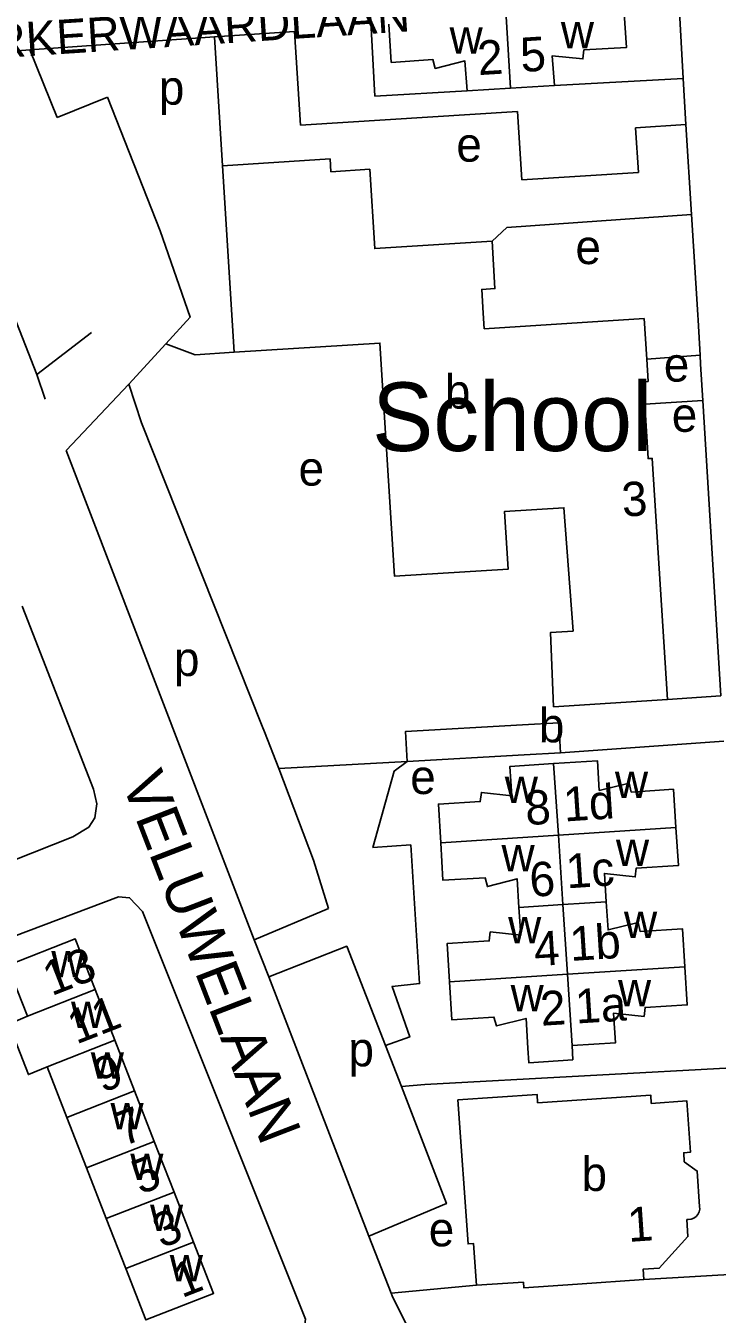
# Model space of a CAD drawing. Extents: x 159675 to 162108, y 386471 to 388472.
# Drawn here: x 160273.4 to 160354.1, y 387507.9 to 387658.2 of the extents above; entities that cross this region are included whole.
import ezdxf

# ---------------------------------------------------------------- set-up
doc = ezdxf.new("R2010")
doc.units = 0
for name, color, linetype in [('BLT_Basislijn', 7, 'Continuous'), ('BLT_Bebouwing', 7, 'Continuous'), ('BLT_Bebouwing_beschrifting', 7, 'Continuous'), ('BLT_Centroide', 7, 'Continuous'), ('BLT_Huisnummer', 7, 'Continuous'), ('BLT_Huisnummer_ tussenligend', 7, 'Continuous'), ('BLT_Onderverdeling_panden', 7, 'Continuous'), ('BLT_Straatnaam', 7, 'Continuous'), ('BLT_Straatnaam_verkleind', 7, 'Continuous')]:
    doc.layers.add(name, color=color, linetype=linetype)

msp = doc.modelspace()

# ---------------------------------------------------------------- linework, layer by layer
at = {"layer": 'BLT_Basislijn'}
for p, q in [((160312.42, 387682.86), (160314.09, 387650.02)), ((160273.87, 387655.42), (160295.39, 387656.92)), ((160295.39, 387656.92), (160304.73, 387657.57)), ((160295.39, 387656.92), (160296.34, 387641.9)), ((160304.73, 387657.57), (160305.42, 387646.63)), ((160273.87, 387655.42), (160268.65, 387655.02)), ((160273.87, 387655.42), (160277.03, 387647.51)), ((160335.06, 387651.26), (160350.07, 387652.07)), ((160350.07, 387652.07), (160350.39, 387646.69)), ((160324.88, 387650.63), (160314.09, 387650.02)), ((160277.03, 387647.51), (160282.91, 387649.88)), ((160305.42, 387646.63), (160330.75, 387648.23)), ((160331.26, 387640.23), (160330.75, 387648.23)), ((160350.39, 387646.69), (160344.53, 387646.32)), ((160344.53, 387646.32), (160344.86, 387641.09)), ((160274.68, 387617.54), (160264.83, 387642.61)), ((160344.86, 387641.09), (160331.26, 387640.23)), ((160351.05, 387636.2), (160351.78, 387624.49)), ((160281.06, 387622.42), (160274.68, 387617.54)), ((160285.41, 387616.39), (160289.72, 387621.11)), ((160345.84, 387619.34), (160352.05, 387619.79)), ((160275.66, 387614.64), (160274.68, 387617.54)), ((160278.08, 387608.68), (160285.41, 387616.39)), ((160345.59, 387614.09), (160352.36, 387614.52)), ((160354.48, 387580.05), (160352.36, 387614.52)), ((160300.04, 387551.59), (160278.08, 387608.68)), ((160348.24, 387579.61), (160354.48, 387580.05)), ((160335.78, 387573.39), (160354.84, 387574.74)), ((160317.87, 387572.39), (160302.89, 387571.55)), ((160308.7, 387555.24), (160300.04, 387551.59)), ((160301.74, 387547.27), (160300.04, 387551.59)), ((160313.41, 387517), (160301.74, 387547.27)), ((160316, 387510.37), (160313.41, 387517)), ((160345.48, 387511.95), (160358.81, 387512.71)), ((160325.97, 387511.3), (160316, 387510.37))]:
    msp.add_line(p, q, dxfattribs=at)
for points in [[(160350.07, 387652.07), (160348.33, 387683.87), (160348.64, 387684.98)], [(160282.91, 387649.88), (160289.07, 387634.3), (160292.57, 387624.22), (160289.72, 387621.11)], [(160351.05, 387636.2), (160350.39, 387646.69)], [(160327.78, 387633.09), (160329.51, 387634.7), (160351.05, 387636.2)], [(160351.78, 387624.49), (160351.82, 387623.88), (160352.05, 387619.79)], [(160289.72, 387621.11), (160293.14, 387619.85), (160297.71, 387620.13)], [(160352.05, 387619.79), (160352.11, 387618.74), (160352.36, 387614.52)], [(160300.98, 387576.52), (160286.9, 387611.91), (160285.41, 387616.39)], [(160225.28, 387549.74), (160227.62, 387544.2), (160234.82, 387546.54), (160262.65, 387557.18), (160278.86, 387563.59), (160280.74, 387564.74), (160281.44, 387565.8), (160281.66, 387567.45), (160281.28, 387569.14), (160273.3, 387589.61), (160272.95, 387590.5)], [(160302.89, 387571.55), (160301.24, 387575.85), (160300.98, 387576.52)], [(160315.35, 387539.24), (160318.18, 387540.26), (160316.12, 387546.15), (160319.32, 387546.48), (160318.29, 387562.65), (160313.89, 387562.37), (160316.38, 387571.27), (160317.87, 387572.39)], [(160308.7, 387555.24), (160306.96, 387560.89), (160302.89, 387571.55)], [(160279.46, 387491.22), (160280.02, 387491.49), (160298.16, 387499.55), (160303.51, 387501.62), (160305.61, 387504), (160306.01, 387507.33), (160287.01, 387554.89), (160285.5, 387556.48), (160284.21, 387556.61), (160258.21, 387546.8)], [(160315.35, 387539.24), (160310.84, 387550.83), (160301.74, 387547.27)], [(160317.22, 387534.45), (160315.35, 387539.24)], [(160317.22, 387534.45), (160319.95, 387534.71), (160357.2, 387536.71)], [(160313.41, 387517), (160322.46, 387520.8), (160317.22, 387534.45)], [(160318.2, 387505.88), (160316.12, 387510.05), (160316, 387510.37)]]:
    msp.add_lwpolyline(points, dxfattribs=at)
at = {"layer": 'BLT_Bebouwing'}
for p, q in [((160324.88, 387650.63), (160329.94, 387650.95)), ((160329.94, 387650.95), (160335.06, 387651.26)), ((160296.34, 387641.9), (160297.71, 387620.13)), ((160345.84, 387619.34), (160345.53, 387624.08)), ((160346.01, 387616.73), (160345.84, 387619.34)), ((160334.96, 387578.77), (160348.24, 387579.61)), ((160331.54, 387573.15), (160317.87, 387572.39)), ((160331.54, 387573.15), (160335.78, 387573.39)), ((160281.47, 387545.77), (160283.77, 387539.86)), ((160283.77, 387539.86), (160286.07, 387533.95)), ((160278.17, 387530.87), (160275.87, 387536.78)), ((160286.07, 387533.95), (160288.38, 387528.04)), ((160280.48, 387524.97), (160278.17, 387530.87)), ((160288.38, 387528.04), (160290.68, 387522.14)), ((160282.78, 387519.06), (160280.48, 387524.97)), ((160290.68, 387522.14), (160292.95, 387516.32)), ((160285.05, 387513.24), (160282.78, 387519.06))]:
    msp.add_line(p, q, dxfattribs=at)
for points in [[(160335.06, 387651.26), (160334.81, 387654.73), (160338.39, 387654.35), (160338.51, 387655.4), (160343.45, 387655.68), (160343.15, 387660.24)], [(160315.73, 387658.41), (160316.03, 387653.95), (160320.86, 387654.29), (160321.16, 387653.24), (160324.62, 387654.12), (160324.88, 387650.63)], [(160327.78, 387633.09), (160314.1, 387632.23), (160313.52, 387641.48), (160308.99, 387641.19), (160308.89, 387642.69), (160296.34, 387641.9)], [(160345.53, 387624.08), (160326.87, 387622.87), (160326.75, 387624.7), (160326.58, 387627.47), (160328.12, 387627.57), (160327.78, 387633.09)], [(160297.71, 387620.13), (160314.71, 387621.2), (160316.42, 387593.99), (160329.65, 387594.82), (160329.23, 387601.55), (160336.17, 387601.99), (160337.23, 387587.6), (160334.59, 387587.42), (160334.96, 387578.77)], [(160345.59, 387614.09), (160345.41, 387616.69), (160346.01, 387616.73)], [(160348.24, 387579.61), (160346.47, 387607.75), (160345.99, 387607.72), (160345.59, 387614.09)], [(160317.87, 387572.39), (160317.67, 387575.87), (160331.34, 387576.65)], [(160335.78, 387573.39), (160335.59, 387576.89), (160331.34, 387576.65)], [(160321.79, 387562.9), (160321.53, 387567.42), (160326.41, 387567.7), (160326.54, 387568.77), (160330.11, 387568.37), (160329.87, 387571.81), (160334.97, 387572.14)], [(160334.97, 387572.14), (160340.07, 387572.48), (160340.28, 387569.01), (160343.78, 387569.85), (160344.02, 387568.82), (160348.94, 387569.15), (160349.24, 387564.69)], [(160349.24, 387564.69), (160349.53, 387560.24), (160344.6, 387559.96), (160344.48, 387558.92), (160340.89, 387559.33), (160341.1, 387556.03)], [(160330.92, 387555.36), (160330.7, 387558.7), (160327.24, 387557.8), (160326.98, 387558.82), (160322.05, 387558.53), (160321.79, 387562.9)], [(160341.1, 387556.03), (160341.32, 387552.74), (160344.83, 387553.59), (160345.06, 387552.57), (160349.99, 387552.88), (160350.27, 387548.43)], [(160322.83, 387546.68), (160322.56, 387551.16), (160327.46, 387551.46), (160327.57, 387552.51), (160331.14, 387552.12), (160330.92, 387555.36)], [(160273.57, 387542.69), (160271.26, 387548.6), (160279.16, 387551.68), (160281.47, 387545.77)], [(160350.27, 387548.43), (160350.56, 387543.99), (160345.64, 387543.7), (160345.52, 387542.64), (160341.96, 387543.03), (160342.19, 387539.58), (160337.12, 387539.26)], [(160337.12, 387539.26), (160337.19, 387537.59), (160332.07, 387537.24), (160331.97, 387538.93), (160331.76, 387542.41), (160328.3, 387541.53), (160328.01, 387542.57), (160323.09, 387542.25), (160322.83, 387546.68)], [(160275.87, 387536.78), (160273.69, 387535.86), (160271.4, 387541.73), (160273.57, 387542.69)], [(160352, 387520.48), (160351.73, 387524.59), (160350.2, 387525.69), (160350.15, 387526.73), (160350.93, 387526.79), (160350.52, 387532.78), (160346.35, 387532.49), (160346.29, 387533.47), (160333.1, 387532.57), (160333.03, 387533.55), (160323.81, 387532.91), (160324.99, 387516.1), (160325.63, 387516.14), (160325.97, 387511.3)], [(160350.68, 387518.95), (160351.01, 387518.99), (160351.31, 387519.11), (160351.58, 387519.3), (160351.79, 387519.55), (160351.93, 387519.84), (160352.01, 387520.16), (160352, 387520.48)], [(160345.48, 387511.95), (160345.4, 387513.14), (160347.29, 387513.27), (160350.64, 387516.95), (160350.51, 387518.94), (160350.68, 387518.95)], [(160292.95, 387516.32), (160295.29, 387510.32), (160287.39, 387507.24), (160285.05, 387513.24)], [(160325.97, 387511.3), (160331.44, 387511.63), (160331.48, 387510.99), (160337.77, 387511.42), (160345.48, 387511.95)]]:
    msp.add_lwpolyline(points, dxfattribs=at)
at = {"layer": 'BLT_Onderverdeling_panden'}
for p, q in [((160329.42, 387659.32), (160329.94, 387650.95)), ((160334.97, 387572.14), (160335.52, 387563.79)), ((160349.24, 387564.69), (160335.52, 387563.79)), ((160335.52, 387563.79), (160321.79, 387562.9)), ((160335.52, 387563.79), (160336.05, 387555.7)), ((160336.05, 387555.7), (160330.92, 387555.36)), ((160341.1, 387556.03), (160336.05, 387555.7)), ((160336.05, 387555.7), (160336.58, 387547.56)), ((160350.27, 387548.43), (160336.58, 387547.56)), ((160336.58, 387547.56), (160322.83, 387546.68)), ((160336.58, 387547.56), (160337.12, 387539.26)), ((160273.57, 387542.69), (160281.47, 387545.77)), ((160275.87, 387536.78), (160283.77, 387539.86)), ((160278.17, 387530.87), (160286.07, 387533.95)), ((160280.48, 387524.97), (160288.38, 387528.04)), ((160282.78, 387519.06), (160290.68, 387522.14)), ((160285.05, 387513.24), (160292.95, 387516.32))]:
    msp.add_line(p, q, dxfattribs=at)

# ---------------------------------------------------------------- texts
at = {"layer": 'BLT_Bebouwing_beschrifting'}
msp.add_text('School', height=8, dxfattribs=at).set_placement((160313.79, 387608.61))
at = {"layer": 'BLT_Centroide'}
for s, p in [('w', (160322.83, 387654.97)), ('w', (160335.81, 387655.59)), ('p', (160288.91, 387649.02)), ('e', (160323.62, 387642.37)), ('e', (160337.51, 387630.42)), ('e', (160347.82, 387616.71)), ('b', (160322.28, 387613.55)), ('e', (160348.75, 387610.85)), ('e', (160305.21, 387604.57)), ('p', (160290.68, 387582.36)), ('b', (160333.24, 387574.62)), ('e', (160318.24, 387568.59)), ('w', (160329.27, 387567.53)), ('w', (160342.12, 387568.12)), ('w', (160342.24, 387560.19)), ('w', (160328.89, 387559.56)), ('w', (160329.66, 387551.19)), ('w', (160343.18, 387551.78)), ('w', (160276.37, 387547.19)), ('w', (160342.48, 387543.84)), ('w', (160329.95, 387543.25)), ('w', (160278.67, 387541.28)), ('p', (160311.03, 387536.82)), ('w', (160280.97, 387535.38)), ('w', (160283.27, 387529.47)), ('w', (160285.58, 387523.56)), ('b', (160338.22, 387522.28)), ('w', (160287.88, 387517.62)), ('e', (160320.4, 387515.82)), ('w', (160290.19, 387511.72))]:
    msp.add_text(s, height=4, dxfattribs=at).set_placement(p)
at = {"layer": 'BLT_Huisnummer'}
for s, rotation, p in [('2', 3.5511, (160326.2, 387652.46)), ('5', 3.5511, (160331.2, 387652.82)), ('3', 3.602, (160343.03, 387600.94)), ('8', 3.7485, (160331.77, 387564.95)), ('1d', 3.7485, (160336.23, 387565.38)), ('1c', 3.7883, (160336.52, 387557.58)), ('1b', 3.6573, (160336.96, 387549.11)), ('13', 21.2956, (160276.39, 387544.99)), ('2', 3.5952, (160333.53, 387541.55)), ('1a', 3.5952, (160337.6, 387541.81)), ('9', 21.2918, (160282.31, 387533.69)), ('5', 21.2967, (160286.73, 387521.82)), ('1', 3.9041, (160343.71, 387516.33)), ('1', 21.2932, (160291.59, 387509.76))]:
    msp.add_text(s, height=4, rotation=rotation, dxfattribs=at).set_placement(p)
at = {"layer": 'BLT_Huisnummer_ tussenligend'}
for s, rotation, p in [('6', 3.7883, (160332.28, 387556.58)), ('4', 3.5787, (160332.79, 387548.5)), ('11', 21.2918, (160279.28, 387539.35)), ('7', 21.2967, (160284.77, 387527.45)), ('3', 21.2932, (160289.21, 387515.56))]:
    msp.add_text(s, height=4, rotation=rotation, dxfattribs=at).set_placement(p)
at = {"layer": 'BLT_Straatnaam'}
msp.add_text('VELUWELAAN', height=5, rotation=291.0841, dxfattribs=at).set_placement((160284.51, 387570.04))
at = {"layer": 'BLT_Straatnaam_verkleind'}
msp.add_text('MARKERWAARDLAAN', height=3.9999, rotation=3.7332, dxfattribs=at).set_placement((160261.66, 387653.89))

doc.saveas('drawing.dxf')
